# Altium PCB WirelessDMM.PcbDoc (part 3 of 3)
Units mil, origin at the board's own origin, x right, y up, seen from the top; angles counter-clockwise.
Board outline 6000 x 520 mil, 6 copper layers (Layer 1 - Top Layer, Layer 2 - GND, Layer 3 - Signal, Layer 4 - PWR, Layer 5 - GND, Layer 6 - Bottom Layer), stack 63.468 mil thick; 198 components, 117 nets, 636 pads, 272 vias.
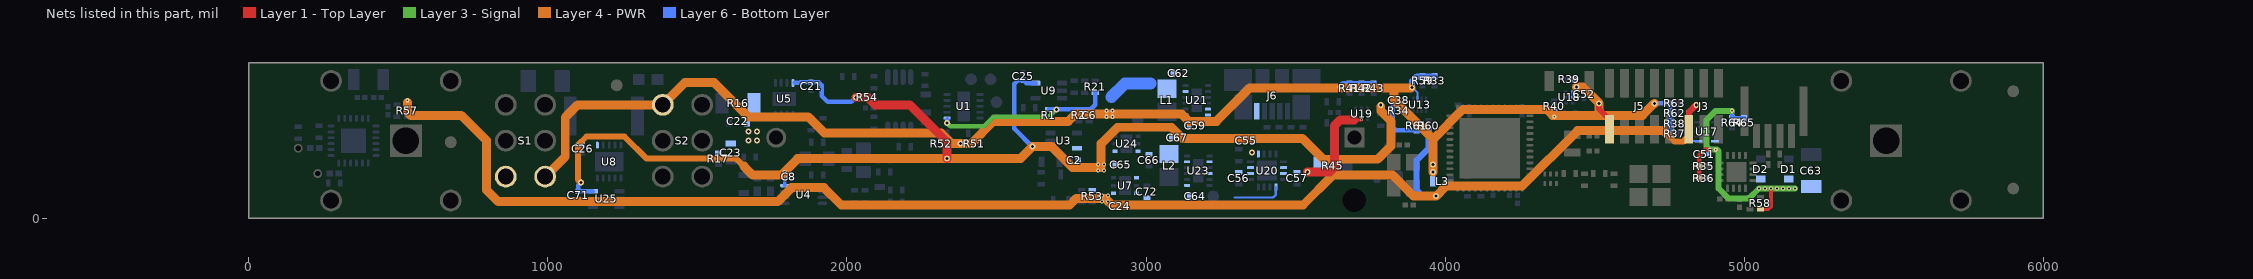
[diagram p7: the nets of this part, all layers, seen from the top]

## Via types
v1: diameter 14, hole 6, Layer 1 - Top Layer to Layer 6 - Bottom Layer, tented both sides, 136 vias
v2: diameter 20, hole 10, Layer 1 - Top Layer to Layer 6 - Bottom Layer, tented both sides, 85 vias
v3: diameter 19.68, hole 7.87, Layer 1 - Top Layer to Layer 6 - Bottom Layer, tented both sides, 35 vias
v4: diameter 19.68, hole 7.87, Layer 1 - Top Layer to Layer 6 - Bottom Layer, 14 vias
v5: diameter 10, hole 6, Layer 1 - Top Layer to Layer 6 - Bottom Layer, tented both sides, 2 vias

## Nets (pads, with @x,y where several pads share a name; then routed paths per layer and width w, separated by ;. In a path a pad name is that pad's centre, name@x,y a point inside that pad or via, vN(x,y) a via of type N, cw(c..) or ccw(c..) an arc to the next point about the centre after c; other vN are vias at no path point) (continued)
V1P9: C52.1 C62.1 J5.1 L1.2 L3.1 R33.2 R37.1 R38.1 R39.2 R40.2 R41.2 R42.2 R43.2 R51.2 R59.2 R62.2 R63.2 S1.3 S2.4 U13.2 U17.1 U18.4 U18.5 U21.5 | length 5405.3
  Layer 1 - Top Layer w20: v2(4515,385) 4515,366 4550,331 J5.1@4550,298.23
  Layer 4 - PWR w30: S1.3@990.94,139.92 1058.01,206.99 1058.01,338.01 1100.08,380.08 S2.4@1384.06,380.08 1458.98,455 1555,455 1670,340 1870,340 1925,285 2315,285 2350,250 v2(2380,250) 2415,250 2490,325 2740,325 2765,350 3118.35,350 3143.35,325 3235,325 3347,437 3830,437 ; v2@3887,437 3830,437 ; v2(3960,155) v2(3960,180) 3960,265 ; v2(4440,440) 4460,440 v2(4515,385) 4515,356 ; v2(4700,385) 4660,345 4360,345 4340,365 4060,365 3960,265 ; 3830,437 3830,395 3960,265
  Layer 6 - Bottom Layer w7: v2(3890,438) 3908.11,419.89 U13.2@3908.11,397.72 ; R37.1@4753.04,283 4753.04,266.96 4761.5,258.5 U17.1@4847.44,258.5
  Layer 6 - Bottom Layer w8: U18.5@4426.81,405 U18.4@4426.81,424.68
  Layer 6 - Bottom Layer w15: v2(2380,250) R51.2@2405,250 ; v1(4365,340) R40.2@4365,360.04 ; v2(4700,385) R63.2@4753.04,385 R62.2@4753.04,351 R38.1@4753.04,317 R37.1@4753.04,283
  Layer 6 - Bottom Layer w20: v2(3649.96,440.04) 3659.88,449.96 R41.2@3680.85,449.96 R42.2@3720.85,449.96 R43.2@3760.85,449.96 ; v2(3890,438) 3890,459 3905.96,474.96 R59.2@3925,474.96 R33.2@3965,474.96
  Layer 6 - Bottom Layer w40: 2884,406 2929,451 3015,451
  other v1: 2868,340 2888,340 2868,360 2888,360
V2P7: C2.2 C8.2 C21.2 C25.2 C26.2 C65.1 C71.2 R52.2 R53.2 R54.2 U3.5 U4.8 U5.8 U8.1 U9.5 U24.1 U25.5 | length 4502.8
  Layer 1 - Top Layer w30: v2(2030,405) 2070,405 2095,380 2210,380 2335,255 v2(2335,200)
  Layer 4 - PWR w20: v1(1100,245.99) 1100,130 v2(1110,120) ; v1@1100.99,245.99 1129.1,274.1 1255.9,274.1 1330,200 1630,200 1655,175
  Layer 4 - PWR w30: 1655,175 1685,145 1780,145 1835,200 1856.7,200 v2(2335,200) 2580,200 v2(2620,240) 2685,240 2755,170 2850,170 2850,250 2905,305 3085,305 3122,268 3522,268 3592,198 3775,198 3820,243 3820,325 3785,360 v2@3785,375
  Layer 6 - Bottom Layer w12: U4.8@1792.01,109.53 C8.2@1792.01,140 v1(1792.01,155)
  Layer 6 - Bottom Layer w15: v1(1100,245.99) C26.2@1116,245.99 ; v2(1110,120) 1101,111 C71.2@1101,90.99 1150.62,90.99 U25.5@1150.71,90.91 ; 1824.85,453.15 1842.15,453.15 1843.99,454.99 C21.2@1880,454.99 1905.01,454.99 1915,445 1915,410 1935,390 2015,390 v2(2030,405) R54.2@2048,405 ; v2(2335,200) R52.2@2335,250 ; v2(2620,240) 2560,300 2560,450 2572.01,462.01 C25.2@2590,462.01 2599.2,452.81 U9.5@2630.71,452.81
  other v1: 2840,160 2860,160 2840,180 2860,180
  other v2: 3785,379
V2P8: C66.1 C67.1 L2.2 U23.5 U24.6
V3P0: C24.1 C38.2 J3.1 R34.1 R57.2 R60.1 R61.2 U7.1 | length 5510.4
  Layer 1 - Top Layer w20: J3.1@4815,298.23 4815,355 v2(4840,380)
  Layer 4 - PWR w20: 4742,283 4767,258 4797,258 4816,277 4816,356 v2(4840,380)
  Layer 4 - PWR w30: 530,388 530,357 542,345 710,345 795,260 795,95 834,56 1768,56 1815,103 1923,103 1981,45 2745,45 2767,67 2863,67 v1(2873,57) 2885,45 3525,45 3625,145 3825,145 3895,75 v2(3970,75) 4003,108 4257,108 4443,294 4731,294 4742,283
  Layer 6 - Bottom Layer w15: R57.2@530,380 v1(530,395) ; C38.2@3832.01,395 3825,388 R34.1@3825,360 3825,306 3835.96,295.04 R61.2@3905,295.04
  Layer 6 - Bottom Layer w20: R61.2@3905,295.04 R60.1@3945,295.04 3945,235 3905,195 3905,95 3925,75 v2(3970,75)
  other v1: 2853,57 2853,77 2873,77
VBAT: C57.1 R45.2 U19.C2 U20.2 U20.3 | length 335.5
  Layer 1 - Top Layer w10: 3695,330 3720.53,330 v5(3720.85,330.32)
  Layer 1 - Top Layer w30: v2(3540,155) 3615,155 3630,170 3630,310 3650,330 3695,330
VBQOUT: C56.1 C59.1 C64.1 C72.1 U7.4 U7.6 U20.5 U20.10 U20.11 U21.1 U21.11 U21.12 U23.1 U23.8 U23.10 | length 166.8
  Layer 6 - Bottom Layer w8: 3297,70 3425,70 3434.53,79.53 U20.5@3434.53,104.88
VOLT_IN: C22.1 C23.2 R16.1 R17.2 S1.6
  other v2: 1670,260 1700,260 1670,290 1700,290
VREF: C6.1 R1.2 R2.2 R21.2 U1.1 | length 632.5
  Layer 3 - Signal w15: v2(2334.88,319) 2345.88,308 2458,308 2490,340 2675,340 v2(2700,365)
  Layer 6 - Bottom Layer w15: v2(2334.88,319) U1.1@2334.88,332 ; v2(2700,365) R1.2@2675,365 R2.2@2775,365 C6.1@2810,365 2815,365 2830,380 R21.2@2830,420
VRF: C51.2 C63.1 D1.1 D2.1 R35.2 R36.2 R58.2 R64.2 R65.2 U17.11 U17.12 | length 923.1
  Layer 1 - Top Layer w12: R58.2@5054.47,31.09 5081.09,31.09 5090,40 v1(5090,100)
  Layer 1 - Top Layer w15: R36.2@4850.04,135 R36.2@4850.04,135 R35.2@4850.04,175 4850.04,210.04 4870,230 v1(4885,230)
  Layer 3 - Signal w20: v1(4960,360) 4905,360 4875,330 4875,240 v1(4885,230) v1(4905,230) 4910,230 4915,225 4915,100 4947.5,67.5 5017.5,67.5 v1(5050,100) v1(5070,100) v1(5090,100) v1(5110,100) v1(5130,100) v1(5150,100) v1(5170,100)
  Layer 6 - Bottom Layer w15: v1(4960,360) R64.2@4960,334.96 R65.2@5000,334.96
VUSB: C55.2 J6.1 U20.13
  other v2: 3355,220
pads on no net: BT1.ALIGN FID1.1 FID2.1 FID3.1 FID4.1 FID5.1 FID6.1 J1.3 J1.5 J2.2 J2.3 J2.4 J2.5 J4.1 J4.4 J4.M1 J4.M2 J5.6 J5.7 J5.8 J6.2 J6.3 J6.4 U7.2 U7.7@2930,92.28 U7.7@2930,127.72 U8.2 U10.20 U10.36 U10.37 U10.38 U10.39 U10.40 U10.41 U10.42 U10.43 U12.2 U12.3 U12.4 U14.14 U14.16 U14.17@4974.47,156.09 U20.7 U20.9 U20.17@3405,160 U21.6 U21.7 U21.13@3170,373.35 U21.13@3170,416.65 U23.6 U23.7 U23.13@3175,138.35 U23.13@3175,181.65 U24.2 U24.7@2935,232.28 U24.7@2935,267.72

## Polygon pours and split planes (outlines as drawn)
GND on Layer 2 - GND "Layer 2 - GND - GND" (solid, remove dead copper, pour order 0): 770,20 4577,20 4577,219 4794,219 4794,20 5980,20 5980,500 770,500 770,350 759,339 531,339 506,364 506,399 500,405 430,405 410,385 410,331 394,315 305,315 305,205 420,205 446,179 757,179 770,166
GND on Layer 5 - GND "Layer 2 - GND - GND" (solid, remove dead copper, pour order 2): 770,20 4577,20 4577,219 4794,219 4794,20 5980,20 5980,500 770,500 770,350 759,339 531,339 506,364 506,399 500,405 430,405 410,385 410,331 394,315 305,315 305,205 420,205 446,179 758,179 770,167
GND on Layer 1 - Top Layer "Layer 1 - Top Layer - GND" (hatched 90Degree grid 48 track 8, remove dead copper, pour order 10): 20,20 770,20 770,500 20,500

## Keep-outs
Keep-Out Layer:
  text ".Layer_Name" at 577,-858.49 h60

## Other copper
Layer 1 - Top Layer:
  region net GND: 5032,23 4961,23 4961,48 5032,48
  region net GND: 4907,180 4938,180 4948,170 5002,170 5012,180 5042,180 5042,199 5017,224 4979,224 4979,194 4973,188 4956,188 4950,194 4950,224 4925,224 4907,206
  region net GND: 4004,161 4052,161 4052,191 4004,191
  region net GND: 3915,160 3915,221 3881,255 3863,255 3863,236 3867,232 3867,160
  region net GND: 3805,130 3855,130 3855,65 3865,55 3877,55 3877,35 3815,35 3805,45
  region net NetC37_1: 4646.81,163 4527,163 4527,137 4646.81,137
  region net NetC28_1: 4207,72 4202,67 4177,67 4172,72 4172,113 4207,113
  region net NetR29_2: 4503,163 4429,163 4429,137 4503,137
  region net NetFL1_1: 4367,137 4405,137 4405,163 4367,163
  region net GND: 4577,20 4285,20 4285,110 4316,110 4316,95 4348,95 4348,175 4368,195 4498,195 4498,284 4520,284 4520,240 4825,240 4825,20 4794,20 4794,219 4577,219 4577,174 4365,174 4358,167 4358,126 4378,126 4577,126
  region net VOLT_IN: 900,125 945,80 1615,80 1640,105 1640,280 1660,300 1705,300 1715,290 1715,255 1685,225 1685,70 1645,30 890,30 820,100 820,165 835,180 885,180 900,165
  text ".Layer_Name" at 577,-858.49 h60
Layer 2 - GND:
  pour cut-out: 4883,368 4892,368 4892,371 4883,371
  region net GND: 4920,368 4859.72,368 4855.86,364.14 4855.86,358.14 4856,358 4920,358
  region net GND: 1058,91 1062,91 1062,121 1058,121
  region net GND: 3707,345 3733,345 3733,350 3707,350
  text ".Layer_Name" at 577,-858.49 h60
Layer 3 - Signal:
  region net GND: 4577,20 4577,126 4577,219 4794,219 4794,20 4825,20 4825,240 4755,240 4735,260 4503,260 4438,195 4380,195 4330,145 4285,145 4285,20
  region net DMM_IN: 470,205 870,205 900,235 900,285 870,315 470,315
  text ".Layer_Name" at 577,-858.49 h60
Layer 4 - PWR:
  region net V2P7: 2863.26,151 2871,158.74 2871,186 2861,196 2841,196 2826,181 2826,161 2836,151
  region net GND: 4577,20 4577,126 4577,219 4794,219 4794,20 4825,20 4825,240 4755,240 4735,260 4445,260 4380,195 4330,145 4285,100 4285,20
  region net V1P9: 2892,333 2896,337 2896,363 2892,367 2864,367 2860,363 2860,337 2864,333
  region net V3P0: 2877,50 2881,54 2881,80 2877,84 2849,84 2845,80 2845,54 2849,50
  text ".Layer_Name" at 577,-858.49 h60
Layer 5 - GND:
  region net GND: 3707,345 3733,345 3733,350 3707,350
  region net GND: 1058,91 1062,91 1062,121 1058,121
  region net GND: 4920,368 4859.72,368 4855.86,364.14 4855.86,358.14 4856,358 4920,358
  pour cut-out: 4883,368 4892,368 4892,371 4883,371
  text ".Layer_Name" at 577,-858.49 h60
Layer 6 - Bottom Layer:
  rectangle net V2P7: 1116,239 1166,254
  rectangle net NetC58_1: 3630,198 3655,338
  rectangle net NetC58_1: 3668.31,140 3707,150
  region net NetC23_1: 1475,155 1510,190 1581,190 1592,201 1629,201 1629,180 1626,177 1607,177 1555,125 1530,100 1500,100 1475,125
  region net CURR_IN: 877,340 960,423 960,497 907,497 818,408 818,351 829,340
  region net NetC10_2: 1902,77 1993,77 2002,68 2155,68 2155,34 1998,34 1968,64 1902,64
  region net IN_P: 2155,82 2012,82 2012,112 2020,120 2155,120
  region net GND: 4031,189 4048,172 4092,172 4107,157 4107,93 4224,93 4224,162 4268,206 4268,355 4266,357 4031,357
  region net GND: 378,380 378,376.5 423.5,376.5 427,380 427,415 378,415
  region net GND: 5265,236.3 5265,171.3 5185,171.3 5185,236.3
  region net IN_P: 1688,122 1684,126 1684,220 1725,220 1761,220 1775.5,205.5 1775.5,180 1765,169.5 1765,130 1757,122
  region net IN_P: 1893,305 1893,137 1889,133 1872,133 1840,165 1840,295 1850,305
  region net IN_P: 2117,183 2097,183 2078,202 1982,202 1982,246 1991,255 2110,255 2117,248
  region net NetR6_1: 2175,40 2195,40 2195,110 2175,110
  region net NetR7_1: 2135,140 2155,140 2155,210 2135,210
  region net NetR8_1: 1935,325 1865,325 1865,340 1870,345 1930,345 1935,340
  region net GND: 3898,383 3848,383 3848,389 3848,395 3848,408 3898,408
  region net NetR34_2: 3912,373 3912,351 3908,347 3857,347 3857,373
  region net V1P9: 4418,476 4418,418 4474,418 4474,444 4442,476
  region net V1P9: 3980,105 3980,180 3965,195 3950,195 3935,180 3935,105
  region net NetC69_1: 4000,105 4090,105 4090,150 4000,150
  region net NetC13_2: 1902,83 1963,83 2015,135 2105,135 2117,147 2117,168 2090,168 2082,176 1981,176 1950,145 1950,107 1939,96 1902,96
  region net NetC15_2: 1902,103 1902,305 1935,305 1965,275 1965,182 1934,151 1934,107 1930,103
  region net NetC22_2: 1625,315 1615,305 1555,305 1520,340 1495,340 1475,360 1475,400 1495,420 1605,420 1625,400
  region net VBAT: 3610,210 3545,210 3510,175 3448,175 3448,144 3610,144
  region net VUSB: 3381,386 3381,315 3381,203 3357,203 3340,220 3340,299 3361,320 3361,386
  region net VBQOUT: 3362,145 3295,145 3285,135 3285,93 3305,73 3305,67 3268,30 3161,30 3129.5,61.5 2976.5,61.5 2959,79 2959,92 3021,92 3026,97 3026,122 3019.5,128.5 2959,128.5 2959,142 3012.5,142 3024,142 3038,128 3038,97 3043,92 3101,92 3125,116 3147,116 3160,103 3160,60 3175,45 3245,45 3255,55 3260,60 3260,92 3260,126 3241,145 3202,145 3202,156 3230,156 3240,166 3240,174 3230,184 3202,184 3202,195 3230,195 3240,205 3240,245 3230,255 3179,255 3120,314 3120,352 3141,352 3160,333 3160,300 3175,285 3200,285 3210,295 3210,325 3195,340 3195,371 3239,371 3280,330 3280,185 3290,175 3362,175
  region net GND: 3614.5,307 3597.5,290 3392.5,290 3392.5,313 3455.5,313 3464.5,322 3464.5,406 3450.5,420 3370.5,420 3355,404.5 3355,330.5 3324.5,300 3324.5,224 3295.5,224 3295.5,340 3240,395.5 3240,501 3626.5,501 3626.5,346 3614.5,334
  region net GND: 3218,380 3188,380 3188,335 3196,327 3196,299 3192,295 3178,295 3172,301 3172,334 3152,354 3152,380 3122,380 3122,411 3152,411 3152,460 3140,472 3120,472 3120,498 3158,498 3188,468 3188,430 3218,430
  region net GND: 3118,276 3130,276 3193,213 3193,63 3191,61 3172,61 3170,63 3170,109 3157,122 3157,145 3127,145 3127,175 3157,175 3157,216 3147,226 3131,226 3118,239
  region net NetL1_1: 3143,371 3044,371 3044,349 3105,349 3116,360 3143,360
  region net NetL2_1: 3148.26,135.72 3049.26,135.72 3049.26,113.72 3106.72,113.72 3117.72,124.72 3148.26,124.72
  region net V2P8: 3149,184 3049,184 3025.5,207.5 2965,207.5 2965,231 3021,231 3056,266 3109,266 3109,212 3126,195 3149,195
  region net V1P9: 3143,419 2964,419 2964,432 2991,432 3000,441 3000,462 2991.5,470.5 2964,470.5 2964,484 2978,498 3057,498 3104,498 3104,445 3119,430 3143,430
  region net V1P9: 2906,432 2882,432 2860,410 2860,330 2906,330
  region net NetR20_1: 1275,485 1252,485 1251,270 1239,258 1239,233 1252,233 1270,233 1273,230 1287,230 1325,268 1325,485
  region net NetF1_2: 1076,497 1022,497 1022,423 1050,395 1050,276 1058,268 1072,268 1080,276 1191,276 1200,267 1200,233 1210,233 1210,434 1147,497
  region net VRF: 5035,145 5035,100 5055,80 5260,80 5260,145
  region net VRF: 4871,206 4871,271 4878,271 4886,263 4915,263 4917,261 4917,232 4891,206
  region net GND: 4577,20 4285,20 4285,112 4392,219 4457,219 4498,260 4520,260 4735,260 4755,240 4825,240 4825,20 4794,20 4794,219 4577,219 4577,174 4577,126
  region net GND: 223,333 237,347 326,347 326,310 334,302 366,302 374,310 374,347 385,347 385,310 392,303 392,244 400,236 434,236 437,233 437,173 335,173 335,210 332,213 302,213 293,204 263,204 263,216 290,216 302,228 302,241 298,245 263,245 263,255 298,255 302,259 302,280 298,284 265,284 249,300 223,300
  pour cut-out: 445,180 270,180 270,340 445,340
  pour cut-out: 371,340 392,340 392,359 371,359
  region net COM: 1808,96 1769,96 1755,110 1638,110 1626,122 1626,155 1620,161 1610,161 1604,155 1604,105 1644,65 1751,65 1769,83 1808,83
  region net VOLT_IN: 1558,222 1558,228 1653,323 1653,408 1665,420 1711,420 1711,253 1702,244 1651,244 1629,222 1593,222 1583,212 1558,212
  region net GND: 4426.81,385.31 4422.31,385.31 4418,381 4418,347 4427,338 4449,338 4492,381 4492,394.06 4474.06,412 4453.5,412
  region net NetR9_1: 1637,134 1637,207 1650,220 1673,220 1673,134
  region net V3P0: 2901,91 2901,28 2855,28 2845,38 2845,81 2855,91
  region net GND: 2680,144 2699,125 2721,125 2757,161 2757,203 2752,208 2738,208 2731,215 2719,215 2712,208 2691,208 2680,197
  region net V2P7: 2752,243 2752,228 2763,217 2763,187 2807,143 2807,87 2832,87 2868,123 2868,146 2882,160 2899,160 2906,167 2906,231 2855,231 2842,218 2800,218 2787,231 2787,243
  region net NetBT1_1: 3663,304 3737,304 3788,253 3824.22,253 3824.49,253.27 3828,249.76 3828,217 3823.57,212.57 3752.43,212.57 3738,227 3672,227 3662,237
  region net NetC58_1: 3641,145 3697,145 3723,119 3782,119 3787,124 3787,154.88 3768.88,173 3725,173 3690,208 3641,208
  region net NetC58_1: 3630,198 3630,187.5 3641.5,176 3650.61,176 3668.31,193.7 3668.31,211.35 3651.07,228.58
  region net NetC58_1: 3630,187.5 3630,153 3643,140 3668.31,140 3668.31,168.31 3675,175 3655,195 3651,195
  region net NetC58_1: 3668.31,211.35 3677.65,202 3662,202 3655,195 3650.59,199.41 3650.59,204.54
  text ".Layer_Name" at 577,-858.49 h60

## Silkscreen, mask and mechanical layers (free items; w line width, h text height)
Top Overlay:
  drawing of 1205 lines, arcs and shapes, not listed
  text "I" at 859,460 h40
  text "RESET" at 4360,370 h40
  text "V" at 849,33 h40
  text "50mV" at 1403,33 h40
  text ".Layer_Name" at 577,-858.49 h60
Bottom Overlay:
  drawing of 1208 lines, arcs and shapes, not listed
  text ".Layer_Name" at 577,-858.49 h60
Top Paste:
  text ".Layer_Name" at 577,-858.49 h60
Bottom Paste:
  text ".Layer_Name" at 577,-858.49 h60
Top Solder:
  text ".Layer_Name" at 577,-858.49 h60
  text ".Layer_Name" at 577,-858.49 h60
Bottom Solder:
  text ".Layer_Name" at 577,-858.49 h60
Drill Guide:
  text ".Layer_Name" at 577,-858.49 h60
M1 Board Outline:
  the board outline again, w10
  text ".Layer_Name" at 577,-858.49 h60
M2 Board Dimensions:
  rectangle: 125,-400 500,-275
  rectangle: 0,-275 125,-150
  lines w7: 0,-275 1000,-275 ; 125,-400 125,-150 ; 250,-400 250,-150 ; 500,-400 500,-150 ; 750,-400 750,-150 ; 0,-400 0,-150 1000,-150 1000,-400 0,-400
  text ".Layer_Name" at 577,-858.49 h60
M3 3D STEP Top:
  text ".Layer_Name" at 577,-858.49 h60
M4 3D STEP Bottom:
  text ".Layer_Name" at 577,-858.49 h60
M5 Assembly Top:
  lines w10: -292,-930.17 6308,-930.17 ; -292,-726.83 6310,-726.83 ; -292,-523.5 -292,-1133.5 3713,-1133.5 6310,-1133.5 6310,-523.5 -291.5,-523.5 -291.5,-1133.5 1284,-1133.5 ; 2173,-1133.5 2173,-523.5 ; 3440,-726.83 3440,-523.5 ; 4280,-726.83 4280,-523.5 ; 4902,-1140 4902,-937.17
  text "COMPONENTS MARKED 'DNP' SHOULD NOT BE POPULATED." at 1153.5,-318.5 h60
  text "ASSEMBLY VARIANT:" at 1153,-434 h60
  text ".VariantName" at 2189,-434 h60
  text "PCB VIEWED FROM TOP SIDE" at -228.5,-655.67 h60
  text "BOARD #:" at 2248,-655.67 h60
  text ".PRJ_Number" at 2793.5,-655.67 h60
  text "REV:" at 3638,-655.67 h60
  text ".PCB_Rev" at 3929.5,-655.67 h60
  text "SVN REV:" at 4476,-655.67 h60
  text ".VersionControl_RevNumber" at 4982,-655.67 h60
  text "TID #:" at 2248,-859 h60
  text ".TID" at 2793.5,-859 h60
  text "PLOT NAME =" at -228.5,-1064.34 h60
  text ".plot_File_Name" at 577,-1064.34 h60
  text "GENERATED    :" at 2250,-1064.34 h60
  text ".Print_Date" at 3119.5,-1064.34 h60
  text ".Print_Time" at 3848.5,-1064.34 h60
  text "TEXAS INSTRUMENTS" at 5113,-1064.34 h60
M6 Assembly Bottom:
  lines w10: -292.5,-727.33 6309.5,-727.33 ; -290.5,-930.67 6309.5,-930.67 ; 1115.5,-1140.5 1115.5,-937.67 ; 1737.5,-727.33 1737.5,-524 ; 2577.5,-727.33 2577.5,-524 ; 3844.5,-1134 3844.5,-524 ; 4733.5,-1134 6309,-1134 6309,-524 -292.5,-524 -292.5,-1134 2304.5,-1134 6309.5,-1134 6309.5,-524
  text "COMPONENTS MARKED 'DNP' SHOULD NOT BE POPULATED." at 6102,-318 h60
  text ".VariantName" at 5058,-434 h60
  text "ASSEMBLY VARIANT:" at 6097,-434 h60
  text ".VersionControl_RevNumber" at 1035.5,-656.17 h60
  text "SVN REV:" at 1541.5,-656.17 h60
  text ".PCB_Rev" at 2088,-656.17 h60
  text "REV:" at 2379.5,-656.17 h60
  text ".PRJ_Number" at 3224,-656.17 h60
  text "BOARD #:" at 3769.5,-656.17 h60
  text "PCB VIEWED FROM BOTTOM SIDE" at 6246,-656.17 h60
  text ".TID" at 3224,-859.5 h60
  text "TID #:" at 3769.5,-859.5 h60
  text "TEXAS INSTRUMENTS" at 904.5,-1064.84 h60
  text ".Print_Time" at 2169,-1064.84 h60
  text ".Print_Date" at 2898,-1064.84 h60
  text "GENERATED    :" at 3767.5,-1064.84 h60
  text ".plot_File_Name" at 5440.5,-1064.84 h60
  text "PLOT NAME =" at 6246,-1064.84 h60
M9 Title Sheet:
  drawing of 1178 lines, arcs and shapes, not listed
  text "1" at 739.84,8036.5 h70
  text "2" at 3235.5,8036.5 h70
  text "3" at 5724.84,8036.5 h70
  text "4" at 8231.51,8036.5 h70
  text "5" at 10730.5,8036.5 h70
  text "6" at 13235.5,8036.5 h70
  text "A" at -416.5,6893.5 h70
  text "A" at 14383.5,6893.5 h70
  text "B" at -416.5,4513.5 h70
  text "B" at 14383.5,4513.5 h70
  text "C" at -416.5,2138.5 h70
  text "C" at 14383.5,2138.5 h70
  text "PROJECT TITLE:" at 11343.5,277.5 h45
  text ".PRJ_Title" at 11393.5,144.17 h70
  text "DESIGNED FOR:" at 11343.5,-23.5 h45
  text ".PRJ_Customer" at 11393.5,-163.5 h70
  text "D" at -416.5,-231.5 h70
  text "D" at 14383.5,-231.5 h70
  text "FILE NAME:" at 11343.5,-323.5 h45
  text ".PCB_File_Name_No_Path" at 11393.5,-443.5 h70
  text "Texas Instruments (TI) and/or its licensors do not warrant the accuracy or completeness of this specification" at 6374,-605.34 h45
  text "ENGINEER:" at 11343.5,-613.5 h45
  text "LAYOUT BY:" at 12848.5,-613.5 h45
  text "or any information contained therein. TI and/or its licensors do not warrant that this design will meet" at 6329.01,-718 h45
  text ".PRJ_Engineer" at 11393.5,-768.49 h70
  text ".PCB_Layout" at 12899,-768.49 h70
  text "JMM" at 12852,-800 h100
  text "s  o  l  u  t  i  o  n  s" at 13710,-803 h68
  text "the specifications, will be suitable for your application or fit for any particular purpose, or will operate in" at 6329.01,-830.67 h45
  text ".Layer_Name" at 577,-858.49 h60
  text "ALTIUM DESIGNER VERSION:" at 12848.5,-923.5 h45
  text "an implementation. TI and/or its licensors do not warrant that the design is production worthy. You should" at 6329.01,-943.33 h45
  text "completely validate and test your design implementation to confirm the system functionality for your application." at 6374,-1056 h45
  text ".print_Scale" at 11393.5,-1056.83 h70
  text ".Application_BuildNumber" at 12899,-1056.83 h70
  text "1" at 739.84,-1263.5 h70
  text "2" at 3235.5,-1263.5 h70
  text "3" at 5724.84,-1263.5 h70
  text "4" at 8231.51,-1263.5 h70
  text "5" at 10730.5,-1263.5 h70
  text "6" at 13235.5,-1263.5 h70
M10 Fab Notes:
  drawing of 174 lines, arcs and shapes, not listed
  text "DESIGN INFORMATION" at 12378.02,6201 h60
  text "MIN. TRACK WIDTH:" at 11733.46,6021 h60
  text "6" at 12829.7,6021 h60
  text "MIL" at 12984.46,6021 h60
  text "MIN. CLEARANCE:" at 11733.46,5889 h60
  text "0.2" at 12769.7,5889 h60
  text "mm" at 12984.46,5889 h60
  text "MIN. VIA PAD SIZE:" at 11733.46,5757 h60
  text "10" at 12799.71,5757 h60
  text "MIL" at 12984.46,5757 h60
  text "Fabrication Notes:" at 6245,5725 h200
  text "0.05mm (2MIL)" at 12428.46,5615.29 h60
  text "MINIMUM ANNULAR RING" at 11404.23,5611 h60
  text "EXTERNAL" at 13136.46,5611 h60
  text "Via Fill - 6 mil vias must be filled with non-conductive epoxy." at 6245,5565 h150
  text "PER" at 11604.23,5493 h60
  text "IPC-D-275 CLASS 2 LEVEL C" at 11824.23,5493 h60
  text "Via Tenting - All vias are to be fully tented on top and bottom solder layers." at 6245,5425 h150
  text "MIL, HOLES" at 13312.46,5380.71 h60
  text "+/-" at 12920,5380 h60
  text "+/-" at 13774,5380 h60
  text "REGISTRATION TOLERANCES:" at 11404.23,5375 h60
  text "METAL" at 12604,5375 h60
  text "5" at 13180.2,5375 h60
  text "3" at 14013.2,5375 h60
  text "MIL" at 14129.46,5375 h60
  text "Impedance Control - Top layer contains 50 ohm (+/- 10%) single ended" at 6245,5285 h150
  text "+/-" at 13774,5262 h60
  text "HOLE SIZE TOLERANCE (UNLESS OTHERWISE SPECIFIED):" at 11404.23,5257 h60
  text "3" at 14013.2,5257 h60
  text "MIL" at 14129.46,5257 h60
  text "impedance using 26 mil shapes (from U12 to FL1)." at 6245,5145 h150
  text "MATERIAL:" at 11329.46,5047.54 h60
  text "FR-4 High Tg" at 12315.9,4907.21 h60
  text "FR-408" at 11750.46,4898.64 h60
  text "OTHER" at 13238.46,4898.64 h60
  text "X" at 12161,4895 h60
  text "62 MIL (1.6mm) +/-10%" at 12070.56,4735.92 h60
  text "THICKNESS:" at 11404.23,4731.64 h60
  text "X" at 11942.4,4731.64 h60
  text "OTHER" at 13355.46,4731.64 h60
  text "TOLERANCE:" at 11404.23,4573.64 h60
  text "X" at 12243.53,4573.64 h60
  text "ANSI IPC-6012 TYPE 3 CLASS 2" at 12430.48,4573.64 h60
  text "OTHER +/-" at 12430.46,4417.64 h60
  text "BOW & TWIST:" at 11404.23,4260.64 h60
  text "X" at 12243.53,4260.64 h60
  text "ANSI IPC-6012 TYPE 3 CLASS 2" at 12430.48,4260.64 h60
  text "OTHER +/-" at 12430.46,4102.13 h60
  text "DRILLING:" at 11329.46,3963.64 h60
  text "REFERENCE:" at 11404.23,3846.64 h60
  text "X" at 12052.46,3846.64 h60
  text "AS SHOWN" at 12239.46,3846.64 h60
  text "X" at 12953.46,3846.64 h60
  text "NC_DRILL FILES" at 13090.46,3846.64 h60
  text "PTH COPPER THICKNESS:" at 11404.23,3688.64 h60
  text "X" at 12534.46,3688.64 h60
  text "20-30 um" at 12671.46,3688.64 h60
  text "OTHER" at 13388.46,3688.64 h60
  text "BOARD FINISH:" at 11329.46,3529.64 h60
  text "SILKSCREEN:" at 11484.68,3411.64 h60
  text "X" at 12433.46,3411.64 h60
  text "TOP" at 12559.46,3411.64 h60
  text "X" at 12943.46,3411.64 h60
  text "BOTTOM" at 13070.46,3411.64 h60
  text "SILKSCREEN COLOR:" at 11484.68,3244.64 h60
  text "X" at 12432.42,3244.64 h60
  text "WHITE" at 12559.46,3244.64 h60
  text "OTHER" at 13070.46,3244.64 h60
  text "X" at 12563.42,3085.44 h60
  text "GREEN" at 12690.46,3085.44 h60
  text "OTHER" at 13308.46,3085.44 h60
  text "SOLDER RESIST COLOR:" at 11484.68,3074.64 h60
  text "X" at 12563.42,2915.44 h60
  text "MATTE" at 12690.46,2915.44 h60
  text "SEMI-GLOSS" at 13308,2914.8 h60
  text "IMMERSION GOLD (ENIG)" at 12390.46,2726.92 h60
  text "ENEPIG" at 13728,2723.64 h60
  text "SURFACE FINISH:" at 11329.46,2722.64 h60
  text "X" at 12203.51,2722.64 h60
  text "IMM. TIN/SILVER OR EQUIV" at 11659,2565.64 h60
  text "OTHER" at 13090.46,2565.64 h60
  text "ARRAY/PANEL:" at 11329.46,2386.64 h60
  text "CUT AND TRIM PER M1 BOARD OUTLINE" at 12390.46,2382.35 h60
  text "N.C. ROUTE" at 12390.46,2230.64 h60
  text "X" at 13069.46,2230.64 h60
  text "V. SCORE" at 13256.46,2230.64 h60
  text "CERTIFICATION:" at 11329.46,2093.64 h60
  text "MATERIALS AND WORKMANSHIP FOR ALL PCBS" at 12054.46,2093.64 h60
  text "TO MEET OR EXCEED THE REQUIREMENTS OF:" at 12054.46,1995.64 h60
  text "X" at 11680.96,1859.13 h60
  text "ANSI IPC-A-600F CLASS ->" at 11819.96,1859.13 h60
  text "X" at 13459.02,1859.13 h60
  text "2" at 13577.96,1859.14 h60
  text "1" at 13262.96,1857.64 h60
  text "3" at 13931.96,1857.64 h60
  text "X" at 12495.02,1699.64 h60
  text "RoHS" at 12631.96,1699.64 h60
  text "OTHER" at 13276.36,1699.64 h60
  text "PER ORDER" at 13673.42,1699.64 h60
  text "ALL BOARDS MUST MEET OR EXCEED UL94-V0 REQUIREMENTS." at 11357,1534 h60
  text "PCB MUST BEAR THE UL94V-0 UL REGISTERED MATERIAL ID NUMBER" at 11357,1414 h60
  text "ADDITIONAL REQUIREMENTS:" at 11329.46,1240.64 h60
  text "MICROSECTION:" at 11404.23,1125.64 h60
  text "YES" at 12309.96,1125.64 h60
  text "REQUIRED" at 13171.46,969.49 h60
  text "BARE BOARD ELEC. TEST:" at 11404.23,966.64 h60
  text "NONE" at 12709.96,966.64 h60
  text "X" at 13044.46,966.64 h60
  text "PER ORDER" at 13763.46,966.64 h60
  text ".Layer_Name" at 577,-858.49 h60
M11 Gerber Information:
  lines w10: -292,-930.17 6308,-930.17 ; -292,-726.83 6310,-726.83 ; -292,-523.5 -292,-1133.5 3713,-1133.5 6310,-1133.5 6310,-523.5 -291.5,-523.5 -291.5,-1133.5 1284,-1133.5 ; 2173,-1133.5 2173,-523.5 ; 3440,-726.83 3440,-523.5 ; 4280,-726.83 4280,-523.5 ; 4902,-1140 4902,-937.17
  text "ALL ARTWORK VIEWED FROM TOP SIDE" at -228.5,-655.67 h60
  text "BOARD #:" at 2248,-655.67 h60
  text ".PRJ_Number" at 2793.5,-655.67 h60
  text "REV:" at 3638,-655.67 h60
  text ".PCB_Rev" at 3929.5,-655.67 h60
  text "SVN REV:" at 4476,-655.67 h60
  text ".VersionControl_RevNumber" at 4982,-655.67 h60
  text "LAYER NAME =" at -228.5,-858.49 h60
  text "TID #:" at 2248,-859 h60
  text ".TID" at 2793.5,-859 h60
  text "PLOT NAME =" at -228.5,-1064.34 h60
  text ".plot_File_Name" at 577,-1064.34 h60
  text "GENERATED    :" at 2250,-1064.34 h60
  text ".Print_Date" at 3119.5,-1064.34 h60
  text ".Print_Time" at 3848.5,-1064.34 h60
  text "TEXAS INSTRUMENTS" at 5113,-1064.34 h60
M12 Stackup:
  drawing of 399 lines, arcs and shapes, not listed
  text "Layer" at 6302.5,7842.5 h60
  text "Name" at 6712.41,7842.5 h60
  text "Material" at 8122,7842.5 h60
  text "Thickness" at 8981.77,7842.5 h60
  text "Constant" at 9631.6,7842.5 h60
  text "Board Layer Stack" at 10201.47,7842.5 h60
  text "1" at 6302.5,7722.5 h60
  text "Top Overlay" at 6712.41,7722.5 h60
  text "2" at 6302.5,7602.5 h60
  text "Top Solder" at 6712.41,7602.5 h60
  text "Solder Resist" at 8122,7602.5 h60
  text "0.40mil" at 8981.77,7602.5 h60
  text "3.5" at 9631.6,7602.5 h60
  text "3" at 6302.5,7482.5 h60
  text "Layer 1 - Top Layer" at 6712.41,7482.5 h60
  text "Copper" at 8122,7482.5 h60
  text "1.40mil" at 8981.77,7482.5 h60
  text "4" at 6302.5,7362.5 h60
  text "Dielectric 1" at 6712.41,7362.5 h60
  text "370HR" at 8122,7362.5 h60
  text "15.00mil" at 8981.77,7362.5 h60
  text "4.2" at 9631.6,7362.5 h60
  text "5" at 6302.5,7242.5 h60
  text "Layer 2 - GND" at 6712.41,7242.5 h60
  text "Copper" at 8122,7242.5 h60
  text "1.42mil" at 8981.77,7242.5 h60
  text "6" at 6302.5,7122.5 h60
  text "Dielectric 2" at 6712.41,7122.5 h60
  text "370HR" at 8122,7122.5 h60
  text "10.00mil" at 8981.77,7122.5 h60
  text "4.2" at 9631.6,7122.5 h60
  text "7" at 6302.5,7002.5 h60
  text "Layer 3 - Signal" at 6712.41,7002.5 h60
  text "Copper" at 8122,7002.5 h60
  text "1.42mil" at 8981.77,7002.5 h60
  text "8" at 6302.5,6882.5 h60
  text "Dielectric 3" at 6712.41,6882.5 h60
  text "370HR" at 8122,6882.5 h60
  text "5.00mil" at 8981.77,6882.5 h60
  text "4.2" at 9631.6,6882.5 h60
  text "9" at 6302.5,6762.5 h60
  text "Layer 4 - PWR" at 6712.41,6762.5 h60
  text "Copper" at 8122,6762.5 h60
  text "1.42mil" at 8981.77,6762.5 h60
  text "10" at 6302.5,6642.5 h60
  text "Dielectric 4" at 6712.41,6642.5 h60
  text "370HR" at 8122,6642.5 h60
  text "10.00mil" at 8981.77,6642.5 h60
  text "4.2" at 9631.6,6642.5 h60
  text "11" at 6302.5,6522.5 h60
  text "Layer 5 - GND" at 6712.41,6522.5 h60
  text "Copper" at 8122,6522.5 h60
  text "1.42mil" at 8981.77,6522.5 h60
  text "12" at 6302.5,6402.5 h60
  text "Dielectric 5" at 6712.41,6402.5 h60
  text "370HR" at 8122,6402.5 h60
  text "15.00mil" at 8981.77,6402.5 h60
  text "4.2" at 9631.6,6402.5 h60
  text "13" at 6302.5,6282.5 h60
  text "Layer 6 - Bottom Layer" at 6712.41,6282.5 h60
  text "Copper" at 8122,6282.5 h60
  text "1.40mil" at 8981.77,6282.5 h60
  text "14" at 6302.5,6162.5 h60
  text "Bottom Solder" at 6712.41,6162.5 h60
  text "Solder Resist" at 8122,6162.5 h60
  text "0.40mil" at 8981.77,6162.5 h60
  text "3.5" at 9631.6,6162.5 h60
  text "15" at 6302.5,6042.5 h60
  text "Bottom Overlay" at 6712.41,6042.5 h60
  text ".Layer_Name" at 577,-858.49 h60
M13 Component Bodies Top:
  text ".Layer_Name" at 577,-858.49 h60
M14 Component Bodies Bottom:
  text ".Layer_Name" at 577,-858.49 h60
M15 Courtyards Top:
  text ".Layer_Name" at 577,-858.49 h60
M16 Courtyards Bottom:
  text ".Layer_Name" at 577,-858.49 h60
Drill Drawing:
  circle w10: c7000.8,700.7 r27.66
  lines w10: 6973.14,189.04 6986.97,189.04 7000.8,175.21 7014.63,189.04 7028.46,189.04 7014.63,202.87 7028.46,216.7 7014.63,216.7 7000.8,230.52 6986.97,216.7 6973.14,216.7 6986.97,202.87 6973.14,189.04 ; 6973.14,354.98 7028.46,354.98 7000.8,299.67 6973.14,354.98 ; 6973.14,437.96 6986.97,437.96 6986.97,424.13 7014.63,424.13 7014.63,437.96 7028.46,437.96 7028.46,465.61 7014.63,465.61 7014.63,479.44 6986.97,479.44 6986.97,465.61 6973.14,465.61 6973.14,437.96 ; 6973.14,576.24 7000.8,548.59 7028.46,576.24 7000.8,603.9 6973.14,576.24 ; 6973.14,797.5 7000.8,811.33 7028.46,797.5 7014.63,825.16 7028.46,852.82 7000.8,838.99 6973.14,852.82 6986.97,825.16 6973.14,797.5 ; 6973.14,921.96 6973.14,935.79 6986.97,949.62 6973.14,963.45 6973.14,977.28 6986.97,977.28 7000.8,963.45 7014.63,977.28 7028.46,977.28 7028.46,963.45 7014.63,949.62 7028.46,935.79 7028.46,921.96 7014.63,921.96 7000.8,935.79 6986.97,921.96 6973.14,921.96 ; 6973.14,1046.42 7028.46,1046.42 7028.46,1101.74 6973.14,1101.74 6973.14,1046.42
  lines w12: 6923,137.87 10624.05,137.87 ; 6923,1133.54 10624.05,1133.54 ; 7261.17,13.41 7261.17,1258 ; 7593.28,13.41 7593.28,1258 ; 8230.29,13.41 8230.29,1258 ; 8489.64,13.41 8489.64,1258 ; 8865.06,13.41 8865.06,1258 ; 10057.2,13.41 10057.2,1258 ; 6923,13.41 10624.05,13.41 10624.05,1258 6923,1258 6923,13.41
  text "Symbol" at 6997.68,1170.88 h72
  text "Quantity" at 7298.51,1170.88 h72
  text "Finished Hole Size" at 7630.62,1170.88 h72
  text "Plated" at 8267.62,1170.88 h72
  text "Hole Type" at 8526.98,1170.88 h72
  text "Drill Layer Pair" at 8902.4,1170.88 h72
  text "Hole Tolerance" at 10094.54,1170.88 h72
  text "1" at 7298.51,1046.42 h60
  text "77.95mil (1.980mm)" at 7630.62,1046.42 h60
  text "NPTH" at 8267.62,1046.42 h60
  text "Round" at 8526.98,1046.42 h60
  text "Layer 1 - Top Layer - Layer 6 - Bottom Layer" at 8902.4,1046.42 h60
  text "138" at 7298.51,921.96 h60
  text "6.00mil (0.152mm)" at 7630.62,921.96 h60
  text "PTH" at 8267.62,921.96 h60
  text "Round" at 8526.98,921.96 h60
  text "Layer 1 - Top Layer - Layer 6 - Bottom Layer" at 8902.4,921.96 h60
  text "49" at 7298.51,797.5 h60
  text "7.87mil (0.200mm)" at 7630.62,797.5 h60
  text "PTH" at 8267.62,797.5 h60
  text "Round" at 8526.98,797.5 h60
  text "Layer 1 - Top Layer - Layer 6 - Bottom Layer" at 8902.4,797.5 h60
  text "85" at 7298.51,673.04 h60
  text "10.00mil (0.254mm)" at 7630.62,673.04 h60
  text "PTH" at 8267.62,673.04 h60
  text "Round" at 8526.98,673.04 h60
  text "Layer 1 - Top Layer - Layer 6 - Bottom Layer" at 8902.4,673.04 h60
  text "2" at 7298.51,548.59 h60
  text "17.72mil (0.450mm)" at 7630.62,548.59 h60
  text "PTH" at 8267.62,548.59 h60
  text "Round" at 8526.98,548.59 h60
  text "Layer 1 - Top Layer - Layer 6 - Bottom Layer" at 8902.4,548.59 h60
  text "2" at 7298.51,424.13 h60
  text "46.85mil (1.190mm)" at 7630.62,424.13 h60
  text "PTH" at 8267.62,424.13 h60
  text "Round" at 8526.98,424.13 h60
  text "Layer 1 - Top Layer - Layer 6 - Bottom Layer" at 8902.4,424.13 h60
  text "20" at 7298.51,299.67 h60
  text "53.15mil (1.350mm)" at 7630.62,299.67 h60
  text "PTH" at 8267.62,299.67 h60
  text "Round" at 8526.98,299.67 h60
  text "Layer 1 - Top Layer - Layer 6 - Bottom Layer" at 8902.4,299.67 h60
  text "2" at 7298.51,175.21 h60
  text "88.58mil (2.250mm)" at 7630.62,175.21 h60
  text "PTH" at 8267.62,175.21 h60
  text "Round" at 8526.98,175.21 h60
  text "Layer 1 - Top Layer - Layer 6 - Bottom Layer" at 8902.4,175.21 h60
  text "299 Total" at 7298.51,50.75 h60
  text ".Layer_Name" at 577,-858.49 h60
M17 Embedded Cavity:
  text ".Layer_Name" at 577,-858.49 h60
M18 Embedded Assembly:
  text ".Layer_Name" at 577,-858.49 h60
M19 Embedded Keepout:
  text ".Layer_Name" at 577,-858.49 h60

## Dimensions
0,-400 to 1000,-400 on M2 Board Dimensions
0,0 to 6000,0 on M2 Board Dimensions
0,0 to 0,520 on M2 Board Dimensions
